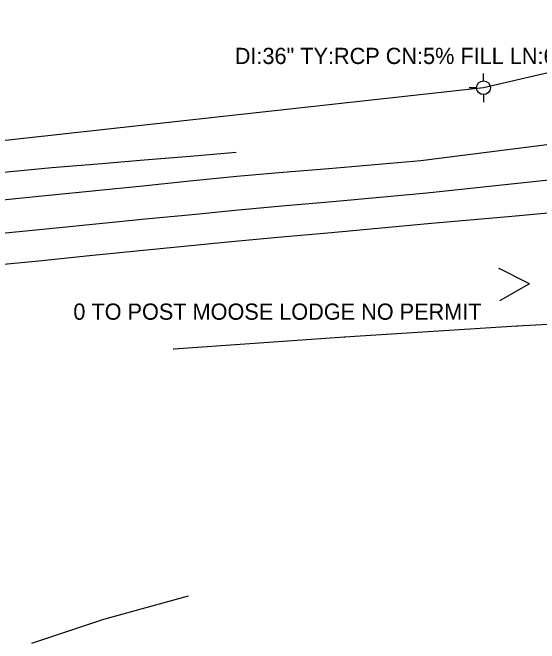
# Model space of a CAD drawing. Extents: x 1707085 to 1720058, y 548761 to 560063.
# Drawn here: x 1712264.3 to 1712426.8, y 550439.8 to 550634.5 of the extents above; entities that cross this region are included whole.
import ezdxf

# ---------------------------------------------------------------- set-up
doc = ezdxf.new("R2010")
doc.units = 0
for name, color, linetype in [('R_Horz Alg Annot', 7, 'Continuous'), ('S_EDGE_PAVEMENT', 7, 'Continuous'), ('S_GAS_UTILITIES', 7, 'Continuous'), ('S_MSC_PT_SYM', 7, 'Continuous'), ('S_PAVEMENT_CROWN', 7, 'Continuous'), ('S_SIDE_DRAIN_ANNOT', 7, 'Continuous'), ('S_SIGN_ANNOT', 7, 'Continuous'), ('S_UTILITY_POLE', 7, 'Continuous'), ('S_UTL_PT_SYM', 7, 'Continuous')]:
    doc.layers.add(name, color=color, linetype=linetype)

msp = doc.modelspace()

# ---------------------------------------------------------------- linework, layer by layer
for points in [[(1712333.26, 550591.33), (1712319.04, 550590.14), (1712304.82, 550588.94), (1712290.6, 550587.74), (1712276.38, 550586.55), (1712260.34, 550585.07), (1712244.29, 550583.59), (1712228.24, 550582.11), (1712212.19, 550580.63), (1712197.88, 550579.13), (1712183.57, 550577.64), (1712169.27, 550576.14), (1712154.96, 550574.65)], [(1712318.48, 550454.39), (1712305.41, 550450.79), (1712292.35, 550447.18), (1712270.08, 550439.84)]]:
    msp.add_lwpolyline(points)
at = {"layer": 'R_Horz Alg Annot'}
for p, q in [((1712423.59, 550550.94), (1712414.37, 550555.5)), ((1712423.6, 550550.7), (1712414.71, 550545.62))]:
    msp.add_line(p, q, dxfattribs=at)
at = {"layer": 'S_EDGE_PAVEMENT'}
for points in [[(1712471.17, 550620.67), (1712467.69, 550612.22), (1712457.04, 550604.08), (1712445.32, 550595.74), (1712431.55, 550593.99), (1712417.79, 550592.25), (1712404.03, 550590.5), (1712390.26, 550588.75), (1712376.07, 550587.54), (1712361.88, 550586.32), (1712347.69, 550585.11), (1712333.49, 550583.89), (1712318.99, 550582.43), (1712304.48, 550580.97), (1712289.98, 550579.51), (1712275.47, 550578.05), (1712261.19, 550576.58), (1712246.9, 550575.1), (1712232.62, 550573.62), (1712218.34, 550572.14), (1712202.94, 550570.5), (1712187.55, 550568.86), (1712172.16, 550567.21), (1712156.76, 550565.57)], [(1712258.21, 550556.53), (1712272.38, 550557.94), (1712286.94, 550559.4), (1712301.51, 550560.87), (1712316.07, 550562.33), (1712330.64, 550563.79), (1712346.08, 550565.18), (1712361.53, 550566.58), (1712376.97, 550567.98), (1712392.42, 550569.37), (1712417.15, 550571.61), (1712441.87, 550573.85), (1712449.92, 550572.7), (1712460.32, 550566.47), (1712469.46, 550551.37), (1712469.35, 550569.93), (1712469.23, 550588.5), (1712469.6, 550612.34)]]:
    msp.add_lwpolyline(points, dxfattribs=at)
at = {"layer": 'S_GAS_UTILITIES'}
for p, q in [((1712464.54, 550540.21), (1712419.89, 550537.7)), ((1712419.89, 550537.7), (1712366.71, 550534.36)), ((1712366.71, 550534.36), (1712313.97, 550530.68))]:
    msp.add_line(p, q, dxfattribs=at)
at = {"layer": 'S_MSC_PT_SYM'}
for points in [[(1712414.37, 550555.5), (1712414.37, 550555.55), (1712414.37, 550555.5), (1712414.32, 550555.5), (1712414.37, 550555.5), (1712414.37, 550555.45), (1712414.37, 550555.5), (1712414.42, 550555.5)], [(1712423.59, 550550.94), (1712423.59, 550550.99), (1712423.59, 550550.94), (1712423.54, 550550.94), (1712423.59, 550550.94), (1712423.59, 550550.89), (1712423.59, 550550.94), (1712423.64, 550550.94)], [(1712423.6, 550550.7), (1712423.6, 550550.75), (1712423.6, 550550.7), (1712423.55, 550550.7), (1712423.6, 550550.7), (1712423.6, 550550.65), (1712423.6, 550550.7), (1712423.65, 550550.7)], [(1712414.71, 550545.62), (1712414.71, 550545.67), (1712414.71, 550545.62), (1712414.66, 550545.62), (1712414.71, 550545.62), (1712414.71, 550545.57), (1712414.71, 550545.62), (1712414.76, 550545.62)]]:
    msp.add_lwpolyline(points, dxfattribs=at)
at = {"layer": 'S_PAVEMENT_CROWN'}
msp.add_lwpolyline([(1712158.89, 550555.88), (1712173.76, 550557.46), (1712188.62, 550559.04), (1712203.49, 550560.63), (1712218.36, 550562.21), (1712232.94, 550563.66), (1712247.53, 550565.11), (1712262.11, 550566.56), (1712276.7, 550568.01), (1712291.01, 550569.42), (1712305.32, 550570.83), (1712319.63, 550572.24), (1712333.93, 550573.64), (1712348.47, 550574.94), (1712363.01, 550576.24), (1712377.55, 550577.54), (1712392.09, 550578.84), (1712404.64, 550580.19), (1712417.19, 550581.55), (1712429.74, 550582.9), (1712442.29, 550584.25), (1712466.13, 550585.96)], dxfattribs=at)
at = {"layer": 'S_UTILITY_POLE'}
for p, q in [((1712409.58, 550613.42), (1712409.58, 550615.67)), ((1712407.49, 550611.29), (1712405.16, 550611.29)), ((1712409.66, 550606.87), (1712409.66, 550609.2))]:
    msp.add_line(p, q, dxfattribs=at)
msp.add_lwpolyline([(1712509.79, 550634.49), (1712409.58, 550611.31), (1712256.35, 550594.36), (1711944.09, 550562.38)], dxfattribs=at)
msp.add_circle((1712409.58, 550611.31), 2.13, dxfattribs=at)
at = {"layer": 'S_UTL_PT_SYM'}
for points in [[(1712419.89, 550537.7), (1712419.89, 550537.75), (1712419.89, 550537.7), (1712419.84, 550537.7), (1712419.89, 550537.7), (1712419.89, 550537.65), (1712419.89, 550537.7), (1712419.94, 550537.7)], [(1712366.71, 550534.36), (1712366.71, 550534.41), (1712366.71, 550534.36), (1712366.66, 550534.36), (1712366.71, 550534.36), (1712366.71, 550534.31), (1712366.71, 550534.36), (1712366.76, 550534.36)], [(1712313.97, 550530.68), (1712313.97, 550530.73), (1712313.97, 550530.68), (1712313.92, 550530.68), (1712313.97, 550530.68), (1712313.97, 550530.63), (1712313.97, 550530.68), (1712314.02, 550530.68)]]:
    msp.add_lwpolyline(points, dxfattribs=at)

# ---------------------------------------------------------------- texts
at = {"layer": 'S_SIDE_DRAIN_ANNOT'}
msp.add_text('DI:36" TY:RCP CN:5% FILL LN:62.', height=5, dxfattribs=at).set_placement((1712332.82, 550618.63))
at = {"layer": 'S_SIGN_ANNOT'}
msp.add_text('0 TO POST MOOSE LODGE NO PERMIT', height=5, dxfattribs=at).set_placement((1712283.02, 550539.71))

doc.saveas('drawing.dxf')
